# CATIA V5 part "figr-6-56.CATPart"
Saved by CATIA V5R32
Part number: Part1
Bounding box of the stored display mesh (mm): x -50.648 to 69.574, y -72.183 to 91.11, z 0 to 52
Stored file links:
  D:\PROJECTS\Project 2022\CATIA V5 6R 2022\Resources\Part Files\c06_catia_v5_6r2022_prt\figr-6-56.CATPart
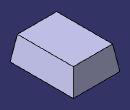
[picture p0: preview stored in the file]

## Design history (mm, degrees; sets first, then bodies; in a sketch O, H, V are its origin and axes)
Body1 (main body)
  Sketch1 on xy-plane, origin (0, 0, 0), H (1, 0, 0), V (0, 1, 0)
    line L1 (-50.6478, 72.1832) -> (50.6478, 72.1832)
    line L2 (50.6478, 72.1832) -> (50.6478, -72.1832)
    line L3 (50.6478, -72.1832) -> (-50.6478, -72.1832)
    line L4 (-50.6478, -72.1832) -> (-50.6478, 72.1832)
    axis line L5 (50.6478, -72.1832) -> (-50.6478, 72.1832)
    horizontal: L1 H, L3 H
    vertical: L2 V, L4 V
    midpoint: O L5
  Pad1: profile Sketch1, direction (0, 0, 1), length 52
  Draft1: Angle 20, Neutral face of Pad1, PullDir edge [face of Pad1 | face of Pad1], SupportToDraft (face of Pad1; face of Pad1)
